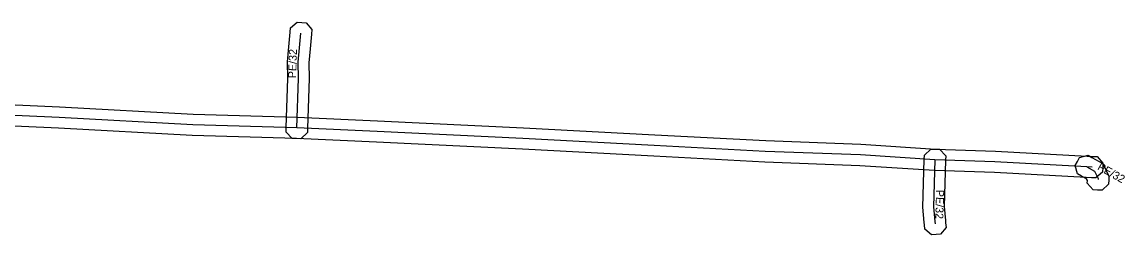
# Model space of a CAD drawing. Extents: x -783553 to -783321, y -1065190 to -1064961.
# Drawn here: x -783439.3 to -783336, y -1064981 to -1064961.1 of the extents above; entities that cross this region are included whole.
import ezdxf

# ---------------------------------------------------------------- set-up
doc = ezdxf.new("R2010")
doc.units = 0
for name, color, linetype in [('1', 7, 'Continuous'), ('30', 7, 'Continuous'), ('Plyn', 7, 'Continuous')]:
    doc.layers.add(name, color=color, linetype=linetype)

msp = doc.modelspace()

# ---------------------------------------------------------------- linework, layer by layer
at = {"layer": '1'}
for points in [[(-783414.56, -1064971.4), (-783414.55, -1064970.99), (-783414.41, -1064966.39), (-783414.42, -1064964.84), (-783414.3, -1064963.44), (-783414.18, -1064962.06), (-783414.14, -1064961.65), (-783413.51, -1064961.12), (-783413.09, -1064961.15), (-783412.68, -1064961.19), (-783412.15, -1064961.82), (-783412.18, -1064962.24), (-783412.3, -1064963.62), (-783412.42, -1064964.92), (-783412.41, -1064966.41), (-783412.55, -1064971.05), (-783412.56, -1064971.46), (-783413.17, -1064972.03), (-783413.58, -1064972.02), (-783413.99, -1064972.01)], [(-783352.75, -1064973.63), (-783352.76, -1064974.04), (-783352.89, -1064978.37), (-783352.77, -1064979.69), (-783352.76, -1064979.9), (-783352.72, -1064980.32), (-783353.25, -1064980.95), (-783353.66, -1064980.99), (-783354.08, -1064981.03), (-783354.71, -1064980.5), (-783354.75, -1064980.08), (-783354.77, -1064979.87), (-783354.89, -1064978.43), (-783354.76, -1064973.98), (-783354.75, -1064973.57), (-783354.14, -1064973), (-783353.73, -1064973.01), (-783353.32, -1064973.02)], [(-783339.49, -1064976.2), (-783339.48, -1064975.95), (-783339.56, -1064975.79), (-783340.03, -1064975.52), (-783340.39, -1064975.31), (-783340.61, -1064974.52), (-783340.41, -1064974.16), (-783340.21, -1064973.8), (-783339.41, -1064973.58), (-783339.05, -1064973.78), (-783338.04, -1064974.35), (-783337.46, -1064975.53), (-783337.47, -1064975.88), (-783337.49, -1064976.29), (-783338.1, -1064976.85), (-783338.52, -1064976.83), (-783338.93, -1064976.81)]]:
    msp.add_lwpolyline(points, close=True, dxfattribs=at)
msp.add_lwpolyline([(-783443.42, -1064968.7), (-783435.78, -1064969.05), (-783423.27, -1064969.74), (-783413.51, -1064970.02), (-783405.98, -1064970.35), (-783392.31, -1064971.02), (-783380.01, -1064971.66), (-783369.61, -1064972.21), (-783360.7, -1064972.55), (-783353.71, -1064973.01), (-783348.1, -1064973.18), (-783339.49, -1064973.65), (-783338.99, -1064973.68), (-783338.57, -1064973.7), (-783338.02, -1064974.32), (-783338.04, -1064974.73), (-783338.06, -1064975.15), (-783338.68, -1064975.7), (-783339.09, -1064975.68), (-783339.59, -1064975.65), (-783348.18, -1064975.18), (-783353.81, -1064975.01), (-783360.8, -1064974.55), (-783369.71, -1064974.21), (-783380.11, -1064973.66), (-783392.41, -1064973.02), (-783406.08, -1064972.35), (-783413.59, -1064972.02), (-783423.35, -1064971.74), (-783435.88, -1064971.05), (-783443.53, -1064970.7)], dxfattribs=at)
at = {"layer": 'Plyn'}
for points in [[(-783413.55, -1064971.02), (-783413.41, -1064966.4), (-783413.42, -1064964.88), (-783413.3, -1064963.53), (-783413.18, -1064962.15)], [(-783339.04, -1064974.68), (-783339.54, -1064974.65), (-783348.14, -1064974.18), (-783353.76, -1064974.01), (-783360.75, -1064973.55), (-783369.66, -1064973.21), (-783380.06, -1064972.66), (-783392.36, -1064972.02), (-783406.03, -1064971.35), (-783413.55, -1064971.02), (-783423.31, -1064970.74), (-783435.83, -1064970.05), (-783443.47, -1064969.7)], [(-783353.76, -1064974.01), (-783353.89, -1064978.4), (-783353.77, -1064979.78), (-783353.75, -1064979.99)], [(-783339.54, -1064974.65), (-783338.8, -1064975.07), (-783338.47, -1064975.74), (-783338.47, -1064975.83)]]:
    msp.add_lwpolyline(points, dxfattribs=at)

# ---------------------------------------------------------------- texts
at = {"layer": '30'}
for rotation, p in [(88.2643, (-783413.62, -1064966.38)), (330.4222, (-783338.6, -1064974.87)), (268.3165, (-783353.65, -1064976.8))]:
    msp.add_text('PE/32', height=0.75, rotation=rotation, dxfattribs=at).set_placement(p)

doc.saveas('drawing.dxf')
